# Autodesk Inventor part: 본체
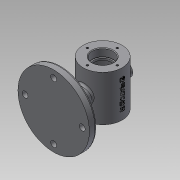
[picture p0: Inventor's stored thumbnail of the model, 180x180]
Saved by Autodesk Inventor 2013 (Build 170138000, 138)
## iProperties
Created: 2018-12
Part Number: 본체
Material: 일반
Document SubType Name: Modeling
Designer: Administrator
Density: 1 g/cm^3
Author: Administrator
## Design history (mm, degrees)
sketch "스케치7"
  geometry: C1 r 30 at (0, 0.503); 1 further point
  constraints: 1 centre point
  dimensions: "d22" = 60 diameter of C1
extrude "돌출5" new body sketch "스케치7" distance "d23" = 70; taper "d24" = 0 deg
sketch "스케치8"
  geometry: C1 r 30 at (0, 0) reference; C2 r 14 at (0, 0); 1 further point
  constraints: 1 centre point, 1 coincident
  dimensions: "d25" = 28 diameter of C2
extrude "돌출6" cut sketch "스케치8" distance "d26" = 70; taper "d27" = 0 deg
sketch "스케치9"
  geometry: C1 r 14 at (0, 0) reference; C2 r 30 at (0, 0) reference; C3 r 16 at (0, 0)
  constraints: 1 centre point, 1 coincident
  dimensions: "d28" = 32 diameter of C3
extrude "돌출7" cut sketch "스케치9" distance "d29" = 12; taper "d30" = 0 deg
sketch "스케치10"
  geometry: C1 r 14 at (0, 0) reference; C2 r 30 at (0, 0) reference; C3 r 16 at (0, 0)
  constraints: 1 centre point, 1 coincident
  dimensions: "d31" = 32 diameter of C3
extrude "돌출8" cut sketch "스케치10" distance "d32" = 12; taper "d33" = 0 deg
sketch "스케치11"
  geometry: L1 (-15.497, 70)-(16.503, 70) reference; L2 (16.503, 0)-(-15.497, 0) reference; L3 (30.503, 0)-(30.503, 70) reference; L4 (0, 35)-(0, 55); L5 (0, 33.432)-(0, 13.432); L6 (14.503, 55)-(25, 55); L7 (14.503, 13.432)-(25, 13.432); L8 (25, 55)-(25, 13.432); L9 (14.503, 58)-(14.503, 12) reference; L10 (14.503, 55)-(14.503, 13.432); L11 (14.503, 58)-(-13.497, 58) reference; L12 (-13.497, 12)-(14.503, 12) reference; L13 (0.503, 70)-(0.503, 53.861); L14 (0.503, 53.861)-(0.503, 0); 1 further point
  constraints: 16 end point, 2 midpoint, 2 perpendicular, 2 point on line, 1 parallel
  dimensions: "d35" = 20 distance of L4.start L4.end; "d36" = 20 distance of L5.start L5.end
revolve "회전1" sketch "스케치11" stored, may be unused: angle "d40" = 90 deg
node "작업 평면1"
sketch "스케치12"
  geometry: L1 (30, 70)-(-30, 70) reference; L2 (-30, 0)-(30, 0) reference; L3 (0, 70)-(0, 35); C1 r 10 at (0, 35); 1 further point
  constraints: 2 end point, 1 centre point, 1 coincident, 1 midpoint, 1 perpendicular
  dimensions: "d42" = 35 distance of L3.start L3.end; "d43" = 20 diameter of C1
extrude "돌출9" join sketch "스케치12" stored distance "d44" = 12; taper "d45" = 0 deg
sketch "스케치13"
  geometry: C1 r 10 at (0, 0) reference; C2 r 5 at (0, 0); 1 further point
  constraints: 1 centre point, 1 coincident
  dimensions: "d46" = 10 diameter of C2
extrude "돌출10" cut sketch "스케치13" stored distance "d47" = 12; taper "d48" = 0 deg
node "작업 평면2"
node "작업 평면3"
sketch "스케치16"
  geometry: L1 (0, -0.503)-(0, -75.503); L2 (0, -75.503)-(0, -66.939); L3 (0, -75.503)-(-55, -75.503); L4 (-55, -75.503)-(-55, -64.503); L5 (-12, -38.003)-(-12, -25.336); L6 (-55, -64.503)-(-26.435, -56.849); L7 (-12, -38.003)-(-12, -52.981); L8 (-26.435, -56.849)-(-12, -52.981); L9 (-12, -25.336)-(0, -27.156); C1 r 30 at (0, 0) reference
  constraints: 18 end point, 2 collinear, 2 perpendicular, 2 point on line, 1 vertical
  dimensions: "d50" = 75 distance of L1.start L1.end; "d51" = 55 distance of L1.end L3.end
revolve "회전2" sketch "스케치16" stored, may be unused: angle "d55" = 90 deg
node "작업 평면4"
sketch "스케치17" dims "d56" = 88
  geometry: C1 r 55 at (0, 0) reference; C2 r 4.5 at (0, 44); C3 r 4.5 at (-44, 0); C4 r 4.5 at (0, -44); C5 r 4.5 at (44, 0); 2 further points
  constraints: 4 centre point, 1 coincident, 1 vertical alignment, 11 other
  dimensions: "d57" = 9 diameter of C2; "d60" = 360 deg dimension on point (0, 0) C2.centre (derived)
extrude "돌출11" cut sketch "스케치17" stored distance "d62" = 23.25; taper "d63" = 0 deg
sketch "스케치18" dims "d64" = 2.5
  geometry: C1 r 55 at (0, 35) reference; 12 further points
  constraints: 24 other
  dimensions: "d68" = 360 deg dimension on C1.centre point (-43.284, 41.963) (derived)
extrude "돌출12" cut sketch "스케치18" distance "d70" = 65; taper "d71" = 0 deg
sketch "스케치19" dims "d72" = 46
  geometry: C1 r 2 at (0, 22.497); C2 r 2 at (-23, -0.503); C3 r 2 at (0, -23.503); C4 r 2 at (23, -0.503); 2 further points
  constraints: 4 centre point, 1 coincident, 1 vertical alignment, 11 other
  dimensions: "d73" = 4 diameter of C1; "d76" = 360 deg dimension on point (0, -0.503) C1.centre (derived)
hole "구멍1" sketch "스케치19" at (0, 22.497), (23, -0.503), (0, -23.503), (-23, -0.503) diameter "d78" = 3.242; stored, may be unused: countersink angle "d82" = 90 deg, drill point angle "d84" = 118 deg; dims "d79" = 8, "d80" = 3.6, "d81" = 2, "d83" = 10
sketch "스케치20"
  geometry: C1 r 23 at (0, -0.503); C2 r 1.621 at (0, 22.497) reference; C3 r 1.621 at (-23, -0.503) reference; C4 r 1.621 at (0, -23.503) reference; C5 r 1.621 at (23, -0.503) reference; 1 further point
  constraints: 1 centre point, 1 coincident
  dimensions: "d85" = 46 diameter of C1
hole "구멍2" sketch "스케치20" at (0, 22.497), (-23, -0.503), (0, -23.503), (23, -0.503) diameter "d86" = 3.242; stored, may be unused: countersink angle "d90" = 90 deg, drill point angle "d92" = 118 deg; dims "d87" = 8, "d88" = 3.6, "d89" = 2, "d91" = 10
fillet "모깎기1" dims "d93" = 0.3, "d94" = 0.3
chamfer "모따기1" distance "d95" = 1; stored, may be unused: second distance "d96" = 2, angle "d97" = 45 deg
fillet "모깎기2" dims "d98" = 3
fillet "모깎기3" dims "d99" = 3
fillet "모깎기4" dims "d100" = 3
node "작업 평면5"
sketch "스케치22"
  geometry: L1 (30, 70)-(-30, 70) reference; L2 (30, 0)-(30, 70) reference; 2 further points
  constraints: 1 other
  dimensions: "d101" = 35 distance from line of point (0, 35) L1; "d102" = 30 distance from line of point (0, 35) L2
feature "엠보싱1" sketch "스케치22" dims "d23" = 70, "d24" = 0, "d103" = 1, "d104" = 0
node "솔리드2"
node "투영된 루프3"
other parameters: "d41" = 37, "d49" = -75
